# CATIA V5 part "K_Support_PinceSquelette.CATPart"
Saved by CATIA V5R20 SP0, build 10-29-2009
Part number: Support_Pince(Squelette)
Publications: "Epaisseur_Cloison", "Epaisseur_LogementVérin", "Epaisseur_Vérin", "Epaisseur_Branche", "Encombrement_Lame", "Distance_Inter_Pivot", "Centre_Pivot_Support1", "Centre_Pivot_Support2", "Plan_Réf_Support", "Plan.2", "Point.3", "Point.4", "Droite.1", "Droite.2", "Droite.3", "Droite.4", "Droite.5"
Bounding box of the stored display mesh (mm): x -30.5 to 30.5, y 0 to 200, z -27 to 0
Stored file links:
  G:\Khaled_CFAO_2011\SIL\SIL_GR1\mneves\Khaled\CAD_CATIA_Modifie\K_Support_PinceSquelette.CATPart
  G:\Khaled_CFAO_2011\SIL\SIL_GR1\mneves\Khaled\CAD_CATIA_Modifie\K_SquePince_A_Bois.CATProduct
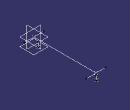
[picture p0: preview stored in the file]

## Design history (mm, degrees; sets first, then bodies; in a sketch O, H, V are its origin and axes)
External parameters (linked from other documents)
  External.Epaisseur_Cloison = 3 mm
  `External.Epaisseur_LogementVérin` = 10 mm
  `External.Epaisseur_Vérin` = 6 mm
  External.Epaisseur_Branche = 15 mm
  External.Encombrement_Lame = 12 mm
  External.Distance_Inter_Pivot = 200 mm
Set1
  Point1 "Centre_Pivot_Support1": linked copy from another document
  Point2 "Centre_Pivot_Support2": linked copy from another document
  Plane1 "Plan_Réf_Support": linked copy from another document
  Plane2: linked copy from another document
  Point3: linked copy from another document
  Point4: linked copy from another document
Set2
  Line1: type PtPt, FirstPoint Point1, SecondPoint Point2
  Line2: type Normal, RefPoint Point1, RefSkin Plane1, Start -30.5, End 30.5 {= External.Epaisseur_Cloison /2+External.Encombrement_Lame +External.Epaisseur_Branche +2mm}
  Line3: type Normal, RefPoint Point2, RefSkin Plane1, Start -30.5, End 30.5 {= External.Epaisseur_Cloison /2+External.Encombrement_Lame +External.Epaisseur_Branche +2mm}
  Line4: type Normal, RefPoint Point3, RefSkin Plane2, Start 0, End 13.5 {= (External.Distance_Inter_Pivot /8+External.Distance_Inter_Pivot /40-External.Epaisseur_Cloison )/2}
  Line5: type Normal, RefPoint Point4, RefSkin Plane2, Start 0, End 13.5 {= (External.Distance_Inter_Pivot /8+External.Distance_Inter_Pivot /40-External.Epaisseur_Cloison )/2}
Body1 (main body)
